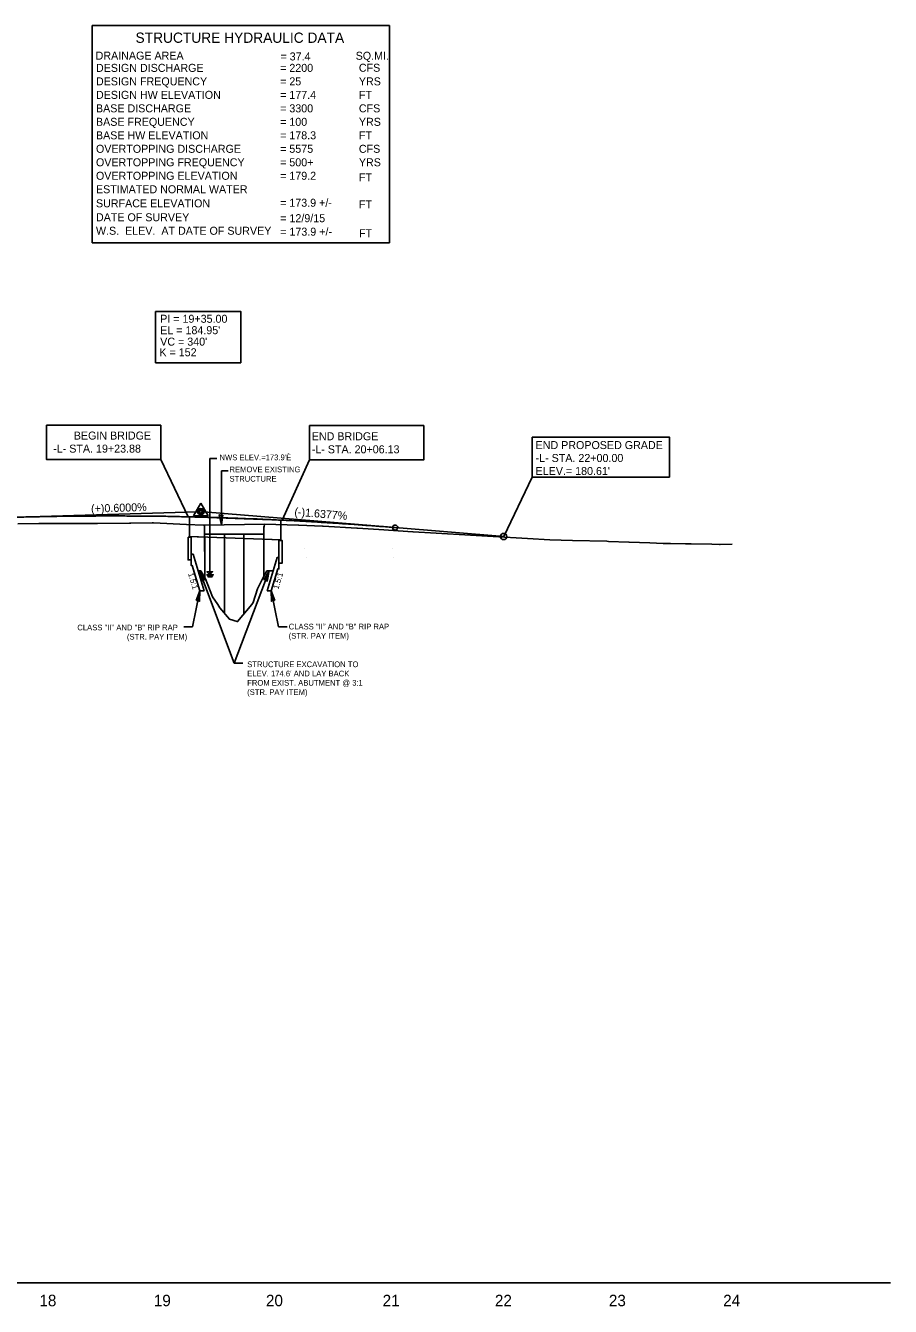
# Model space of a CAD drawing. Extents: x 1726619 to 1729848, y 535683 to 539687.
# Drawn here: x 1729092 to 1729848, y 537992 to 539113 of the extents above; entities that cross this region are included whole.
import ezdxf

# ---------------------------------------------------------------- set-up
doc = ezdxf.new("R2010")
doc.units = 0
for name, color, linetype in [('COGO Default Spiral', 7, 'Continuous'), ('Exist Drainage Structure Bridge', 7, 'Continuous'), ('Exist Profile Cell', 7, 'Continuous'), ('Exist Vertical Profile Horizontal Axis Label Major', 7, 'Continuous'), ('Exist Vertical Profile Horizontal Axis Label Minor', 7, 'Continuous'), ('Exist Vertical Profile Vertical Axis Label', 7, 'Continuous'), ('Prop Dimension', 7, 'Continuous'), ('Prop Dimension Text', 7, 'Continuous'), ('Prop Drainage Structure Bridge Opening Label', 7, 'Continuous'), ('Prop PFL Structure Hydraulic Data Label CELL', 7, 'Continuous'), ('Prop Plan Preparation Excavation Hatching', 7, 'Continuous'), ('Prop Terminator CELL', 7, 'Continuous'), ('Prop Vertical Profile Grade', 7, 'Continuous'), ('Raster_Level_0', 7, 'Continuous'), ('Sheet Cutting Line CELL', 7, 'Continuous'), ('Sheet Profile CELL', 7, 'Continuous'), ('Sheet Profile Grid Major CELL', 7, 'Continuous'), ('Sheet Profile Grid Middle CELL', 7, 'Continuous'), ('Sheet Profile Grid Minor CELL', 7, 'Continuous'), ('Sheet Sticker Incomplete CELL', 7, 'Continuous')]:
    doc.layers.add(name, color=color, linetype=linetype)

msp = doc.modelspace()

# ---------------------------------------------------------------- linework, layer by layer
at = {"layer": 'COGO Default Spiral'}
for p, q in [((1729252.9, 538734.2), (1729258.8, 538734.2)), ((1729252.9, 538632.5), (1729252.9, 538734.2)), ((1729262.9, 538723.6), (1729268.8, 538723.6)), ((1729262.9, 538676.1), (1729262.9, 538723.6))]:
    msp.add_line(p, q, dxfattribs=at)
for points in [[(1729252.9, 538632.5), (1729256, 538632.5), (1729249.9, 538632.5)], [(1729252.9, 538631.6), (1729255.4, 538631.6), (1729250.5, 538631.6)], [(1729252.9, 538630.7), (1729254.8, 538630.7), (1729251.1, 538630.7)]]:
    msp.add_lwpolyline(points, dxfattribs=at)
msp.add_lwpolyline([(1729252.9, 538632.5), (1729250.3, 538635.1), (1729255.2, 538635.1)], close=True, dxfattribs=at)
at = {"layer": 'Exist Drainage Structure Bridge'}
for p, q in [((1729247.9, 538675.8), (1729300.5, 538676.8)), ((1729248.3, 538668), (1729300.1, 538668)), ((1729265.6, 538598.7), (1729265.6, 538668)), ((1729282.6, 538598.4), (1729282.6, 538668))]:
    msp.add_line(p, q, dxfattribs=at)
at = {"layer": 'Exist Profile Cell'}
msp.add_line((1728309.9, 538013), (1729848.2, 538013), dxfattribs=at)
at = {"layer": 'Exist Vertical Profile Horizontal Axis Label Major'}
msp.add_line((1729414.9, 538673.8), (1729509.9, 538666), dxfattribs=at)
msp.add_spline([(1729074.9, 538682.6), (1729081.7, 538682.8), (1729088.5, 538683), (1729095.3, 538683.2), (1729102.1, 538683.3), (1729108.9, 538683.5), (1729115.7, 538683.6), (1729122.5, 538683.7), (1729129.3, 538683.8), (1729136.1, 538683.8), (1729142.9, 538683.9), (1729149.7, 538683.9), (1729156.5, 538684), (1729163.3, 538684), (1729170.1, 538684), (1729176.9, 538684), (1729183.7, 538683.9), (1729190.5, 538683.9), (1729197.3, 538683.8), (1729204.1, 538683.8), (1729210.9, 538683.7), (1729217.7, 538683.6), (1729224.5, 538683.4), (1729231.3, 538683.3), (1729238.1, 538683.1), (1729244.9, 538683), (1729251.7, 538682.8), (1729258.5, 538682.6), (1729265.3, 538682.4), (1729272.1, 538682.1), (1729278.9, 538681.9), (1729285.7, 538681.6), (1729292.5, 538681.4), (1729299.3, 538681.1), (1729306.1, 538680.8), (1729312.9, 538680.4), (1729319.7, 538680.1), (1729326.5, 538679.8), (1729333.3, 538679.4), (1729340.1, 538679), (1729346.9, 538678.6), (1729353.7, 538678.2), (1729360.5, 538677.8), (1729367.3, 538677.3), (1729374.1, 538676.9), (1729380.9, 538676.4), (1729387.7, 538675.9), (1729394.5, 538675.4), (1729401.3, 538674.9), (1729408.1, 538674.4), (1729414.9, 538673.8)], degree=3, dxfattribs=at)
at = {"layer": 'Exist Vertical Profile Horizontal Axis Label Minor'}
for p, q in [((1729335.9, 538655.7), (1729335.9, 538655.7)), ((1729412.2, 538655.7), (1729412.2, 538655.7)), ((1729337, 538647.8), (1729337, 538647.8)), ((1729413.3, 538647.8), (1729413.3, 538647.8))]:
    msp.add_line(p, q, dxfattribs=at)
at = {"layer": 'Exist Vertical Profile Vertical Axis Label'}
for p, q in [((1729209.9, 538733.4), (1729233.8, 538683.2)), ((1729339.9, 538733), (1729316, 538680.3)), ((1729534.9, 538718), (1729509.9, 538666)), ((1729074.9, 538682.6), (1729242.1, 538687.6)), ((1729414.9, 538673.8), (1729247.6, 538687.5))]:
    msp.add_line(p, q, dxfattribs=at)
for centre in [(1729244.9, 538687.7), (1729509.9, 538666)]:
    msp.add_circle(centre, 2.75, dxfattribs=at)
at = {"layer": 'Prop Dimension'}
for p, q in [((1729243.9, 538635.9), (1729274.1, 538555.1)), ((1729304.6, 538635.9), (1729274.1, 538555.1)), ((1729244.2, 538618.4), (1729237.6, 538587.1)), ((1729306.5, 538618.4), (1729313, 538587.1)), ((1729237.6, 538587.1), (1729230.1, 538587.1)), ((1729313, 538587.1), (1729320.6, 538587.1)), ((1729281.7, 538555.1), (1729274.1, 538555.1))]:
    msp.add_line(p, q, dxfattribs=at)
at = {"layer": 'Prop Plan Preparation Excavation Hatching'}
for p, q in [((1729234.9, 538665.5), (1729234.9, 538665.9)), ((1729234.9, 538665.9), (1729248.3, 538665.4)), ((1729314.9, 538663.1), (1729300.1, 538663.6)), ((1729314.9, 538662.6), (1729314.9, 538663.1)), ((1729244.9, 538635.9), (1729242.5, 538635.9)), ((1729248.5, 538629.9), (1729244.9, 538635.9)), ((1729300, 538631.4), (1729302.7, 538635.9)), ((1729302.7, 538635.9), (1729308.1, 538635.9))]:
    msp.add_line(p, q, dxfattribs=at)
for points in [[(1729236.5, 538650.5), (1729236.5, 538665.5), (1729234.9, 538665.5)], [(1729248.3, 538665.4), (1729248.5, 538629.9)], [(1729300.1, 538663.6), (1729300, 538631.4)], [(1729313.3, 538647.6), (1729313.3, 538662.6), (1729314.9, 538662.6)], [(1729242.5, 538635.9), (1729238.1, 538650.5), (1729236.5, 538650.5)], [(1729308.1, 538635.9), (1729311.7, 538647.6), (1729313.3, 538647.6)]]:
    msp.add_lwpolyline(points, dxfattribs=at)
at = {"layer": 'Prop Terminator CELL'}
for points in [[(1729264.3, 538685.1), (1729262.9, 538676.1), (1729261.1, 538685.1), (1729262.7, 538684)], [(1729245.8, 538627), (1729243.9, 538635.9), (1729248.8, 538628.1), (1729246.8, 538628.6)], [(1729300, 538628), (1729304.6, 538635.9), (1729302.9, 538626.9), (1729301.8, 538628.5)], [(1729240.8, 538609.9), (1729244.2, 538618.4), (1729243.9, 538609.2), (1729242.5, 538610.7)], [(1729309.8, 538609.9), (1729306.5, 538618.4), (1729306.8, 538609.2), (1729308.1, 538610.7)]]:
    msp.add_lwpolyline(points, close=True, dxfattribs=at)
at = {"layer": 'Prop Vertical Profile Grade'}
msp.add_lwpolyline([(1729084.8, 538677.2), (1729103.1, 538677.3), (1729105.1, 538677.3), (1729133.1, 538677.3), (1729134.4, 538677.3), (1729152.6, 538677.3), (1729154.6, 538677.3), (1729182.6, 538677.7), (1729183.6, 538677.7), (1729202.3, 538677.9), (1729203.5, 538677.9), (1729232.3, 538676.5), (1729247.4, 538675.8), (1729247.9, 538675.8), (1729247.9, 538675.3), (1729248.2, 538675.5), (1729248.5, 538629.9), (1729248.9, 538629.1), (1729255.2, 538613.2), (1729259.7, 538606.4), (1729261.7, 538603.7), (1729269.9, 538593.7), (1729276.7, 538591.7), (1729277.1, 538591.6), (1729289.6, 538606.4), (1729290.7, 538608.2), (1729294.6, 538620.2), (1729295.7, 538622.6), (1729300, 538631.4), (1729300.2, 538674.7), (1729300.4, 538674.4), (1729300.5, 538676.8), (1729330.5, 538675.8), (1729330.8, 538675.8), (1729351.4, 538675.1), (1729352, 538675), (1729381.4, 538673.3), (1729381.9, 538673.3), (1729400.8, 538672.2), (1729430.3, 538670.2), (1729430.8, 538670.2), (1729450.7, 538668.8), (1729480.9, 538667.1), (1729500.6, 538666), (1729530.6, 538664.3), (1729550.2, 538663.2), (1729570.2, 538662.6), (1729600.1, 538661.8), (1729601.7, 538661.7), (1729619.4, 538661.1), (1729619.7, 538661.1), (1729637.8, 538660.4), (1729649.3, 538660), (1729655.8, 538659.9), (1729668.9, 538659.6), (1729669.4, 538659.6), (1729673.8, 538659.6), (1729691.9, 538659.2), (1729698.7, 538659.1), (1729699.2, 538659.1), (1729709.9, 538659.3)], dxfattribs=at)
at = {"layer": 'Raster_Level_0'}
for p, q in [((1729244.9, 538635.9), (1729242.5, 538635.9)), ((1729248.5, 538629.9), (1729244.9, 538635.9)), ((1729300, 538631.4), (1729302.7, 538635.9)), ((1729302.7, 538635.9), (1729308.1, 538635.9)), ((1729244.2, 538618.4), (1729247.8, 538618.4)), ((1729302.9, 538618.4), (1729306.5, 538618.4))]:
    msp.add_line(p, q, dxfattribs=at)
for points in [[(1729247.8, 538618.4), (1729238.1, 538650.5), (1729236.5, 538650.5), (1729236.5, 538640.5), (1729237.5, 538640.5), (1729244.2, 538618.4)], [(1729302.9, 538618.4), (1729311.7, 538647.6), (1729313.3, 538647.6), (1729313.3, 538637.6), (1729312.3, 538637.6), (1729306.5, 538618.4)]]:
    msp.add_lwpolyline(points, dxfattribs=at)
at = {"layer": 'Sheet Profile CELL'}
for p, q in [((1729244.9, 538695.2), (1729238.4, 538684)), ((1729244.9, 538695.2), (1729251.4, 538684)), ((1729238.4, 538684), (1729251.4, 538684))]:
    msp.add_line(p, q, dxfattribs=at)
for radius in [1.75, 1.2]:
    msp.add_circle((1729244.9, 538687.7), radius, dxfattribs=at)
at = {"layer": 'Sheet Profile Grid Major CELL'}
for points in [[(1729149.9, 538923), (1729409.9, 538923), (1729409.9, 539113), (1729149.9, 539113)], [(1729205.4, 538863), (1729279.9, 538863), (1729279.9, 538818), (1729205.4, 538818)], [(1729109.9, 538763.4), (1729209.9, 538763.4), (1729209.9, 538733.4), (1729109.9, 538733.4)], [(1729339.9, 538763), (1729439.9, 538763), (1729439.9, 538733), (1729339.9, 538733)], [(1729534.9, 538753), (1729654.9, 538753), (1729654.9, 538718), (1729534.9, 538718)]]:
    msp.add_lwpolyline(points, close=True, dxfattribs=at)
at = {"layer": 'Sheet Profile Grid Middle CELL'}
for p, q in [((1729234.9, 538683.2), (1729314.9, 538680.3)), ((1729234.9, 538683.2), (1729234.9, 538665.9)), ((1729314.9, 538680.3), (1729314.9, 538663.1)), ((1729314.9, 538663.1), (1729234.9, 538665.9)), ((1729234.9, 538665.5), (1729234.9, 538665.9)), ((1729314.9, 538662.6), (1729314.9, 538663.1))]:
    msp.add_line(p, q, dxfattribs=at)
for points in [[(1729233.8, 538665.5), (1729236.5, 538665.5), (1729236.5, 538645.5), (1729233.8, 538645.5)], [(1729313.3, 538642.6), (1729316, 538642.6), (1729316, 538662.6), (1729313.3, 538662.6)]]:
    msp.add_lwpolyline(points, close=True, dxfattribs=at)
at = {"layer": 'Sheet Profile Grid Minor CELL'}
msp.add_circle((1729414.9, 538673.8), 2.25, dxfattribs=at)

# ---------------------------------------------------------------- texts
at = {"layer": 'COGO Default Spiral'}
msp.add_text("NWS ELEV.=173.9'È", height=5, rotation=0.0449, dxfattribs=at).set_placement((1729261.3, 538732.7))
at = {"layer": 'Exist Vertical Profile Vertical Axis Label'}
for s, p in [('PI = 19+35.00', (1729209.4, 538853)), ("EL = 184.95'", (1729209.4, 538843))]:
    msp.add_text(s, height=7, dxfattribs=at).set_placement(p)
at = {"layer": 'Prop Dimension Text'}
for s, p in [('REMOVE EXISTING', (1729270, 538722.2)), ('STRUCTURE', (1729270, 538714)), ('CLASS "II" AND "B" RIP RAP', (1729136.9, 538583.9)), ('CLASS "II" AND "B" RIP RAP', (1729321.8, 538584.7)), ('(STR. PAY ITEM)', (1729180.3, 538575.8)), ('(STR. PAY ITEM)', (1729321.8, 538576.6))]:
    msp.add_text(s, height=5, dxfattribs=at).set_placement(p)
for s, p in [('STRUCTURE EXCAVATION TO ', (1729285.5, 538551.7)), ("ELEV. 174.6' AND LAY BACK ", (1729285.5, 538543.6)), ('FROM EXIST. ABUTMENT @ 3:1', (1729285.5, 538535.5)), ('(STR. PAY ITEM)', (1729285.5, 538527.4))]:
    msp.add_text(s, height=5, rotation=360, dxfattribs=at).set_placement(p)
at = {"layer": 'Prop Drainage Structure Bridge Opening Label'}
for rotation, p in [(286.6992, (1729233.7, 538633.5)), (73.3008, (1729312.8, 538619.5))]:
    msp.add_text('1.5:1', height=5, rotation=rotation, dxfattribs=at).set_placement(p)
at = {"layer": 'Prop PFL Structure Hydraulic Data Label CELL'}
for s, height, p in [('STRUCTURE HYDRAULIC DATA', 9, (1729187.8, 539097.9)), ('DRAINAGE AREA', 7, (1729152.9, 539083.2)), ('SQ.MI.', 7, (1729380.4, 539083.1)), ('DESIGN DISCHARGE', 7, (1729153.2, 539072.5)), ('= 2200', 7, (1729314.3, 539072.5)), ('= 37.4', 7, (1729314.6, 539082.5)), ('CFS', 7, (1729383.2, 539072.6)), ('DESIGN FREQUENCY', 7, (1729153.2, 539060.7)), ('= 25', 7, (1729314.3, 539060.7)), ('YRS', 7, (1729383.2, 539060.7)), ('DESIGN HW ELEVATION', 7, (1729153.2, 539048.9)), ('= 177.4', 7, (1729314.3, 539048.9)), ('FT', 7, (1729383.2, 539048.9)), ('BASE DISCHARGE', 7, (1729153.2, 539037.1)), ('= 3300', 7, (1729314.3, 539037.1)), ('CFS', 7, (1729383.2, 539037.1)), ('BASE FREQUENCY', 7, (1729153.2, 539025.3)), ('= 100', 7, (1729314.3, 539025.3)), ('YRS', 7, (1729383.2, 539025.3)), ('BASE HW ELEVATION', 7, (1729153.2, 539013.5)), ('= 178.3', 7, (1729314.3, 539013.5)), ('FT', 7, (1729383.2, 539013.5)), ('OVERTOPPING DISCHARGE', 7, (1729153.2, 539001.7)), ('= 5575', 7, (1729314.3, 539001.7)), ('CFS', 7, (1729383.2, 539001.7)), ('OVERTOPPING FREQUENCY', 7, (1729153.2, 538989.9)), ('= 500+', 7, (1729314.3, 538989.9)), ('YRS', 7, (1729383.2, 538989.9)), ('OVERTOPPING ELEVATION', 7, (1729153.2, 538978.1)), ('= 179.2', 7, (1729314.3, 538978.1)), ('FT', 7, (1729383.2, 538976.7)), ('ESTIMATED NORMAL WATER', 7, (1729153.2, 538966.3)), ('SURFACE ELEVATION', 7, (1729153.2, 538954)), ('= 173.9 +/-', 7, (1729314.3, 538954.5)), ('FT', 7, (1729383.2, 538953.1)), ('FT', 7, (1729383.2, 538953.1)), ('DATE OF SURVEY  ', 7, (1729153.2, 538941.8)), ('= 12/9/15', 7, (1729314.4, 538941)), ('W.S.  ELEV.  AT DATE OF SURVEY', 7, (1729153.2, 538930)), ('= 173.9 +/-', 7, (1729314.4, 538929.2)), ('FT', 7, (1729383.3, 538927.8))]:
    msp.add_text(s, height=height, dxfattribs=at).set_placement(p)
at = {"layer": 'Sheet Cutting Line CELL'}
for s, p in [('18', (1729103.7, 537992.6)), ('19', (1729203.8, 537992.6)), ('20', (1729301.9, 537992.6)), ('21', (1729404, 537992.6)), ('22', (1729502.2, 537992.6)), ('23', (1729601.9, 537992.6)), ('24', (1729701.9, 537992.6))]:
    msp.add_text(s, height=10, dxfattribs=at).set_placement(p)
at = {"layer": 'Sheet Profile Grid Minor CELL'}
for s, p in [("VC = 340'", (1729209.4, 538833)), ('K = 152', (1729208.7, 538823.7)), ('BEGIN BRIDGE', (1729133.8, 538750.8)), ('END BRIDGE', (1729342, 538750.2)), ('-L- STA. 19+23.88', (1729115.8, 538739.4)), ('-L- STA. 20+06.13', (1729342, 538738.8)), ('END PROPOSED GRADE', (1729537.8, 538742.5)), ('-L- STA. 22+00.00', (1729537.8, 538731.2)), ("ELEV.= 180.61'", (1729537.8, 538719.8))]:
    msp.add_text(s, height=7, dxfattribs=at).set_placement(p)
at = {"layer": 'Sheet Sticker Incomplete CELL'}
for s, rotation, p in [('(+)0.6000%', 1.7184, (1729149, 538686.9)), ('(-)1.6377%', 355.3187, (1729326.6, 538684.3))]:
    msp.add_text(s, height=7, rotation=rotation, dxfattribs=at).set_placement(p)

doc.saveas('drawing.dxf')
